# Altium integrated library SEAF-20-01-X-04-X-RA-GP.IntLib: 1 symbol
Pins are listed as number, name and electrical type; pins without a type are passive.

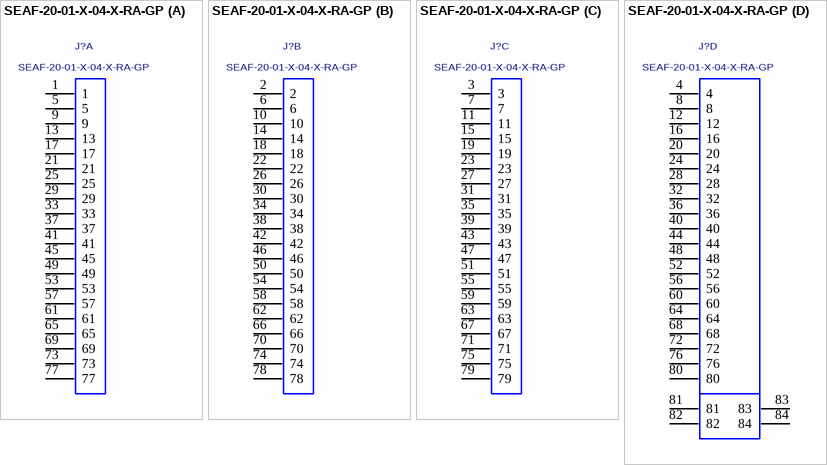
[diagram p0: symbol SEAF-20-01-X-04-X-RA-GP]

## SEAF-20-01-X-04-X-RA-GP
designator J?
SEAF-RA BODY; MANUFACTURER: SAMTEC
footprint SEAF-20-01-X-04-X-RA-GP
part A pins: 1, 5, 9, 13, 17, 21, 25, 29, 33, 37, 41, 45, 49, 53, 57, 61, 65, 69, 73, 77
part B pins: 2, 6, 10, 14, 18, 22, 26, 30, 34, 38, 42, 46, 50, 54, 58, 62, 66, 70, 74, 78
part C pins: 3, 7, 11, 15, 19, 23, 27, 31, 35, 39, 43, 47, 51, 55, 59, 63, 67, 71, 75, 79
part D pins: 4, 8, 12, 16, 20, 24, 28, 32, 36, 40, 44, 48, 52, 56, 60, 64, 68, 72, 76, 80, 81, 82, 83, 84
